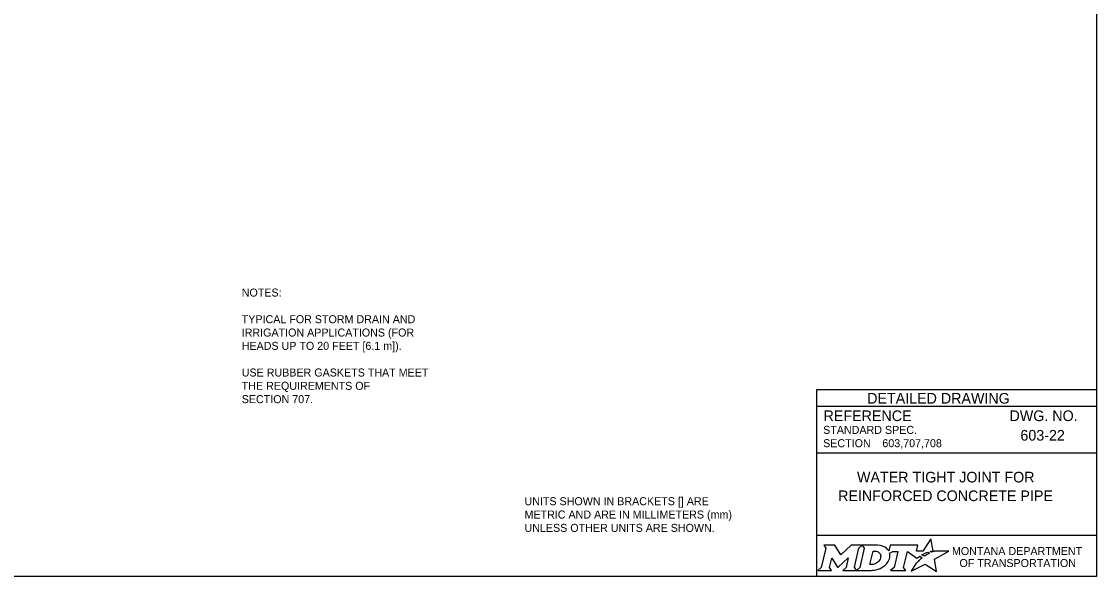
# Model space of a CAD drawing. Extents: x 49991.4 to 50021, y 49987.6 to 50011.4.
# Drawn here: x 50008.69 to 50016.75, y 49987.8 to 49991.96 of the extents above; entities that cross this region are included whole.
import ezdxf

# ---------------------------------------------------------------- set-up
doc = ezdxf.new("R2010")
doc.units = 0
for name, color, linetype in [('Default', 7, 'Continuous'), ('Level 1', 7, 'Continuous'), ('Level 2', 7, 'Continuous'), ('Level 5', 7, 'Continuous')]:
    doc.layers.add(name, color=color, linetype=linetype)

msp = doc.modelspace()

# ---------------------------------------------------------------- linework, layer by layer
at = {"layer": 'Default'}
for points in [[(50015.5126, 49987.9811), (50015.5023, 49987.9867), (50015.5139, 49987.9895), (50015.5255, 49987.9915), (50015.5081, 49988.0816), (50015.4486, 49987.9903), (50015.4013, 49987.9896), (50015.4116, 49988.0337), (50015.2024, 49988.0338), (50015.1923, 49987.9913), (50015.1865, 49987.9996)], [(50014.7056, 49988.0338), (50014.7197, 49988.0104), (50014.6862, 49987.8671), (50014.6605, 49987.8446), (50014.7621, 49987.8446), (50014.7486, 49987.8674), (50014.7648, 49987.9375), (50014.8085, 49987.8685), (50014.8138, 49987.8685), (50014.8889, 49987.938), (50014.8725, 49987.8669), (50014.8478, 49987.8449), (50014.9494, 49987.8449), (50014.9356, 49987.8682), (50014.9688, 49988.0106)], [(50014.9688, 49988.0106), (50014.9941, 49988.0338), (50014.9117, 49988.0338), (50014.8321, 49987.9608), (50014.7876, 49988.0335), (50014.7056, 49988.0338)], [(50015.1077, 49988.0338), (50014.9941, 49988.0338), (50015.0088, 49988.0109), (50014.9749, 49987.8671), (50014.9494, 49987.8449), (50015.06, 49987.8449)], [(50015.1317, 49987.9471), (50015.1305, 49987.939), (50015.1273, 49987.9297), (50015.1231, 49987.9215), (50015.1175, 49987.914), (50015.111, 49987.9071), (50015.1031, 49987.9008), (50015.0948, 49987.8961), (50015.0857, 49987.8922), (50015.0766, 49987.8899), (50015.0674, 49987.889), (50015.0515, 49987.889), (50015.0751, 49987.989), (50015.0911, 49987.989), (50015.0987, 49987.9884), (50015.1063, 49987.9865), (50015.1129, 49987.9835), (50015.119, 49987.9793), (50015.1238, 49987.9743), (50015.1275, 49987.9683), (50015.1302, 49987.9621), (50015.1318, 49987.9547), (50015.1318, 49987.9517), (50015.1317, 49987.9471)], [(50015.1991, 49987.9747), (50015.2237, 49987.9878), (50015.2606, 49987.9878), (50015.232, 49987.8673), (50015.2045, 49987.8446), (50015.3207, 49987.8446), (50015.3037, 49987.8675), (50015.3319, 49987.9877), (50015.4032, 49987.936), (50015.4243, 49987.9511), (50015.444, 49987.9402)], [(50015.3882, 49987.8843), (50015.3729, 49987.8599), (50015.3682, 49987.8524), (50015.3624, 49987.8438), (50015.3601, 49987.8395), (50015.4654, 49987.8926), (50015.5493, 49987.8375), (50015.5362, 49987.9302), (50015.6431, 49987.9886), (50015.5938, 49987.9894), (50015.5637, 49987.9898), (50015.5429, 49987.9901), (50015.5361, 49987.9886), (50015.5312, 49987.9874), (50015.5228, 49987.9851), (50015.5126, 49987.9811)], [(50015.4622, 49987.9535), (50015.4598, 49987.9518), (50015.4415, 49987.9614), (50015.4518, 49987.9671), (50015.4559, 49987.9693), (50015.4645, 49987.9733), (50015.4702, 49987.9759), (50015.4781, 49987.9789), (50015.4854, 49987.9816), (50015.4972, 49987.9742), (50015.4932, 49987.9721), (50015.4886, 49987.9696), (50015.4844, 49987.9674), (50015.4794, 49987.9645), (50015.4775, 49987.9634), (50015.4748, 49987.9618), (50015.4723, 49987.9604), (50015.47, 49987.9588), (50015.4674, 49987.957), (50015.4647, 49987.9552), (50015.4622, 49987.9535)], [(50015.1057, 49987.8522), (50015.1141, 49987.8548), (50015.1271, 49987.8602), (50015.1475, 49987.8712)], [(50015.4021, 49987.9004), (50015.4021, 49987.9004)]]:
    msp.add_lwpolyline(points, dxfattribs=at)
for centre, radius, start, end in [((50015.0868, 49987.9727), 0.1183, 300.91025, 339.13831), ((50015.1308, 49987.9554), 0.0709, 339.53292, 15.85821)]:
    msp.add_arc(centre, radius, start, end, dxfattribs=at)
for centre, major_axis, ratio, start_param, end_param in [((50015.1056, 49987.9864), (0.0834, -0.0037), 0.568097, 0.61298, 1.570796), ((50015.1612, 49987.9937), (0.0361, -0.0295), 0.469099, 1.225588, 1.570796), ((50015.4119, 49987.9106), (-0.0098, -0.0102), 0.016458, 3.141593, 6.279097), ((50015.4329, 49987.9305), (-0.0112, -0.0097), 0.021651, 3.157348, 6.283185), ((50015.0603, 49987.9932), (0, 0.1484), 0.987302, 3.139398, 3.456847), ((50015.3952, 49987.8923), (-0.00694, -0.00806), 0.008222, 0, 3.137361)]:
    msp.add_ellipse(centre, major_axis=major_axis, ratio=ratio, start_param=start_param, end_param=end_param, dxfattribs=at)
at = {"layer": 'Level 1'}
msp.add_lwpolyline([(49999.3835, 49998.9992), (50016.7501, 49998.9992), (50016.7501, 49987.7988), (49999.3835, 49987.7988)], close=True, dxfattribs=at)
at = {"layer": 'Level 5'}
for p, q in [((50016.7501, 49989.1988), (50014.6501, 49989.1988)), ((50014.6501, 49989.1988), (50014.6501, 49987.7988)), ((50016.7501, 49989.0738), (50014.6501, 49989.0738)), ((50016.3862, 49988.8587), (50016.3862, 49988.8587)), ((50016.7501, 49988.7238), (50014.6501, 49988.7238)), ((50015.1444, 49988.7993), (50015.1444, 49988.7993)), ((50015.7001, 49988.4747), (50015.7001, 49988.4747)), ((50016.7501, 49988.1057), (50014.6501, 49988.1057))]:
    msp.add_line(p, q, dxfattribs=at)

# ---------------------------------------------------------------- texts
at = {"layer": 'Default'}
for s, p in [('MONTANA DEPARTMENT', (50015.6663, 49987.96)), ('OF TRANSPORTATION', (50015.7225, 49987.87))]:
    msp.add_text(s, height=0.06, dxfattribs=at).set_placement(p)
at = {"layer": 'Level 2'}
for s, height, p in [('NOTES:', 0.06, (50010.3409, 49989.8999)), ('TYPICAL FOR STORM DRAIN AND ', 0.06, (50010.3409, 49989.6999)), ('IRRIGATION APPLICATIONS (FOR ', 0.06, (50010.3409, 49989.5999)), ('HEADS UP TO 20 FEET [6.1 m]).', 0.06, (50010.3409, 49989.4999)), ('USE RUBBER GASKETS THAT MEET', 0.06, (50010.3409, 49989.2999)), ('THE REQUIREMENTS OF ', 0.06, (50010.3409, 49989.1999)), ('SECTION 707.', 0.06, (50010.3409, 49989.0999)), ('603-22', 0.08, (50016.1796, 49988.8187)), ('603,707,708', 0.06, (50015.1444, 49988.7693)), ('WATER TIGHT JOINT FOR', 0.08, (50014.9544, 49988.5047)), ('REINFORCED CONCRETE PIPE', 0.08, (50014.8126, 49988.3647)), ('UNITS SHOWN IN BRACKETS [] ARE ', 0.06, (50012.4611, 49988.334)), ('METRIC AND ARE IN MILLIMETERS (mm) ', 0.06, (50012.4611, 49988.234)), ('UNLESS OTHER UNITS ARE SHOWN.', 0.06, (50012.4611, 49988.134))]:
    msp.add_text(s, height=height, dxfattribs=at).set_placement(p)
at = {"layer": 'Level 5'}
for s, height, p in [('DETAILED DRAWING', 0.0799, (50015.0311, 49989.0963)), ('REFERENCE', 0.08, (50014.7037, 49988.9654)), ('DWG. NO.', 0.08, (50016.0979, 49988.9654)), ('STANDARD SPEC.', 0.06, (50014.7004, 49988.8694)), ('SECTION', 0.06, (50014.7004, 49988.7694))]:
    msp.add_text(s, height=height, dxfattribs=at).set_placement(p)

doc.saveas('drawing.dxf')
